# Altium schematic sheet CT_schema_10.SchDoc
size 147 x 119 mm
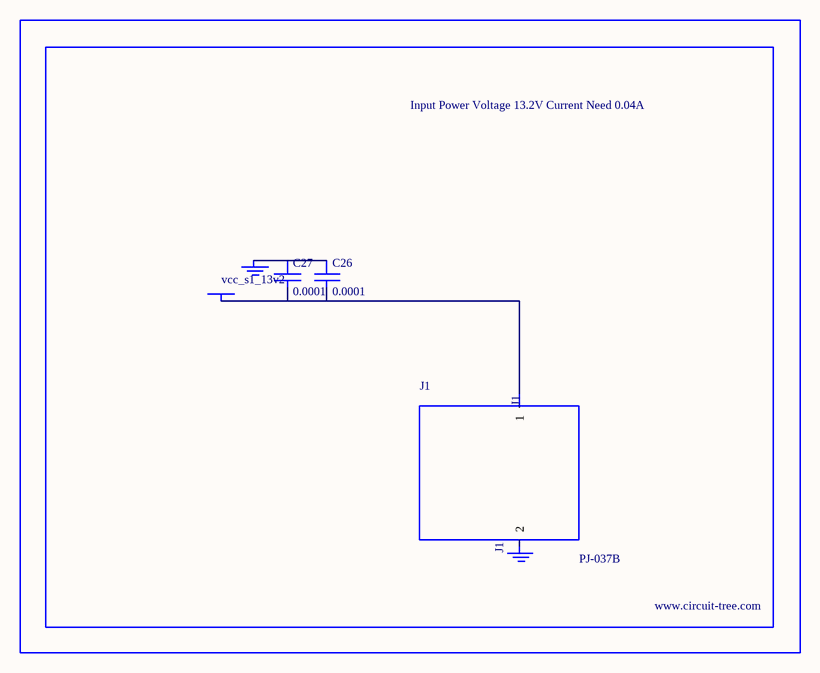
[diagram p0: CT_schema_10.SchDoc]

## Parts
BORDER9  (no value)
C26  0.0001  [EXV-9H]
C27  0.0001  [EXV-9H]
GND_INSTANCE_9_0  (no value)
GND_INSTANCE_9_1  (no value)
J1  PJ-037B  [PJ-037B_PACKAGE]
POWER_INSTANCE_9_0  vcc_s1_13v2

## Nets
NetC26_1: C26.1 C27.1 GND_INSTANCE_9_0.0(GND)
NetC26_2: C26.2 C27.2 J1.1 POWER_INSTANCE_9_0.0(PWR)

Not connected (* = marked no-connect by the designer): GND_INSTANCE_9_1 0(GND); J1 2

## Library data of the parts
BORDER9 = BORDER_PAGE9
C26 C27 = EDK107M035A9HAA
GND_INSTANCE_9_0 GND_INSTANCE_9_1 = GND
POWER_INSTANCE_9_0 = PWR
